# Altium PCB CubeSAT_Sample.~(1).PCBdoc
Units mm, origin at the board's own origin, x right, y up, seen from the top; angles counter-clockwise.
Board outline 90.17 x 95.89 mm, 2 copper layers (Top Layer, Bottom Layer); 6 components, 23 nets, 108 pads, 0 vias.
Unrouted connection lines stored in the file: 25.
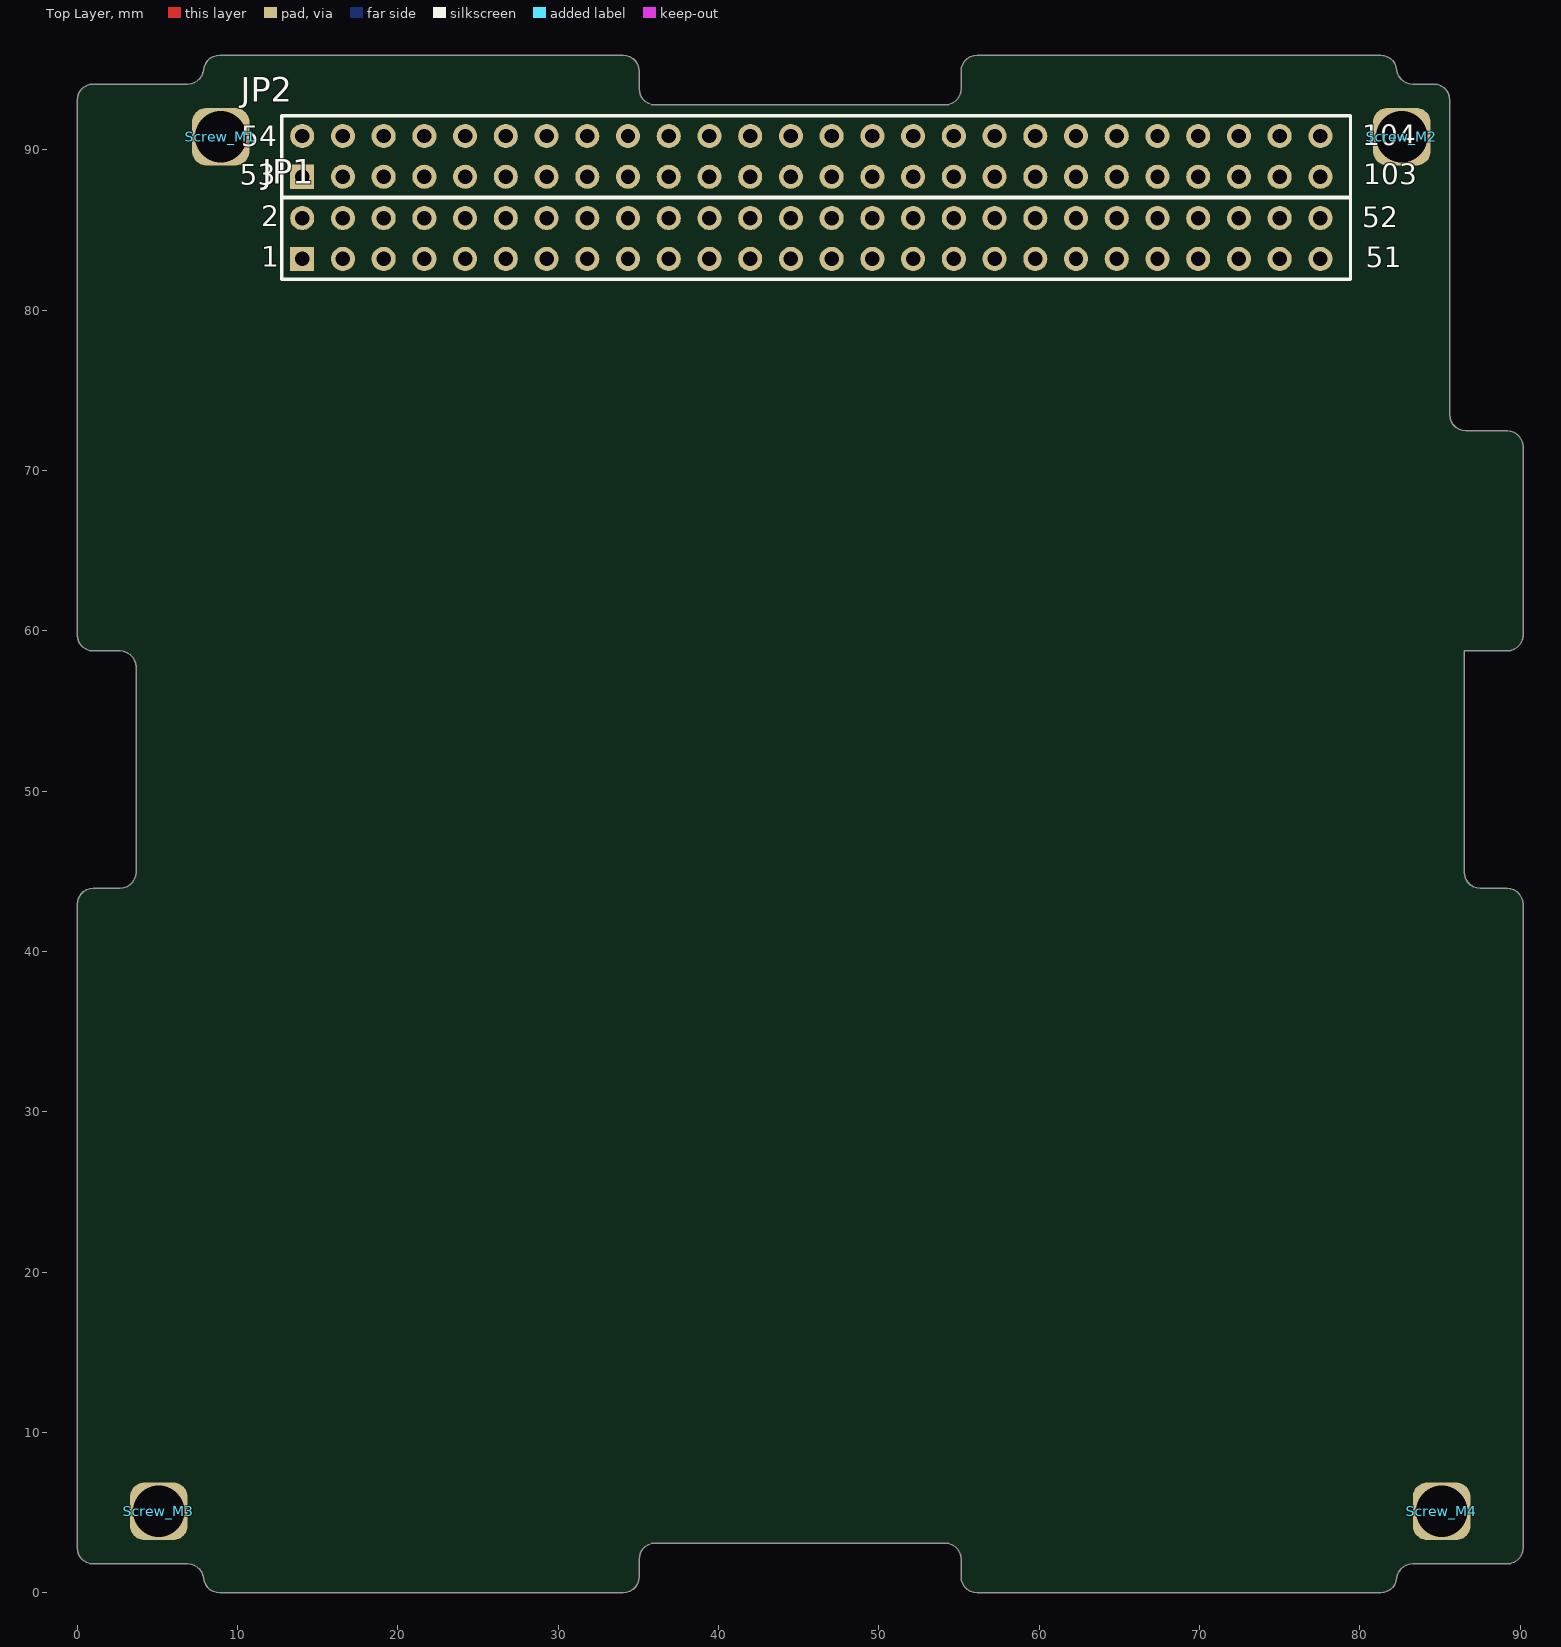
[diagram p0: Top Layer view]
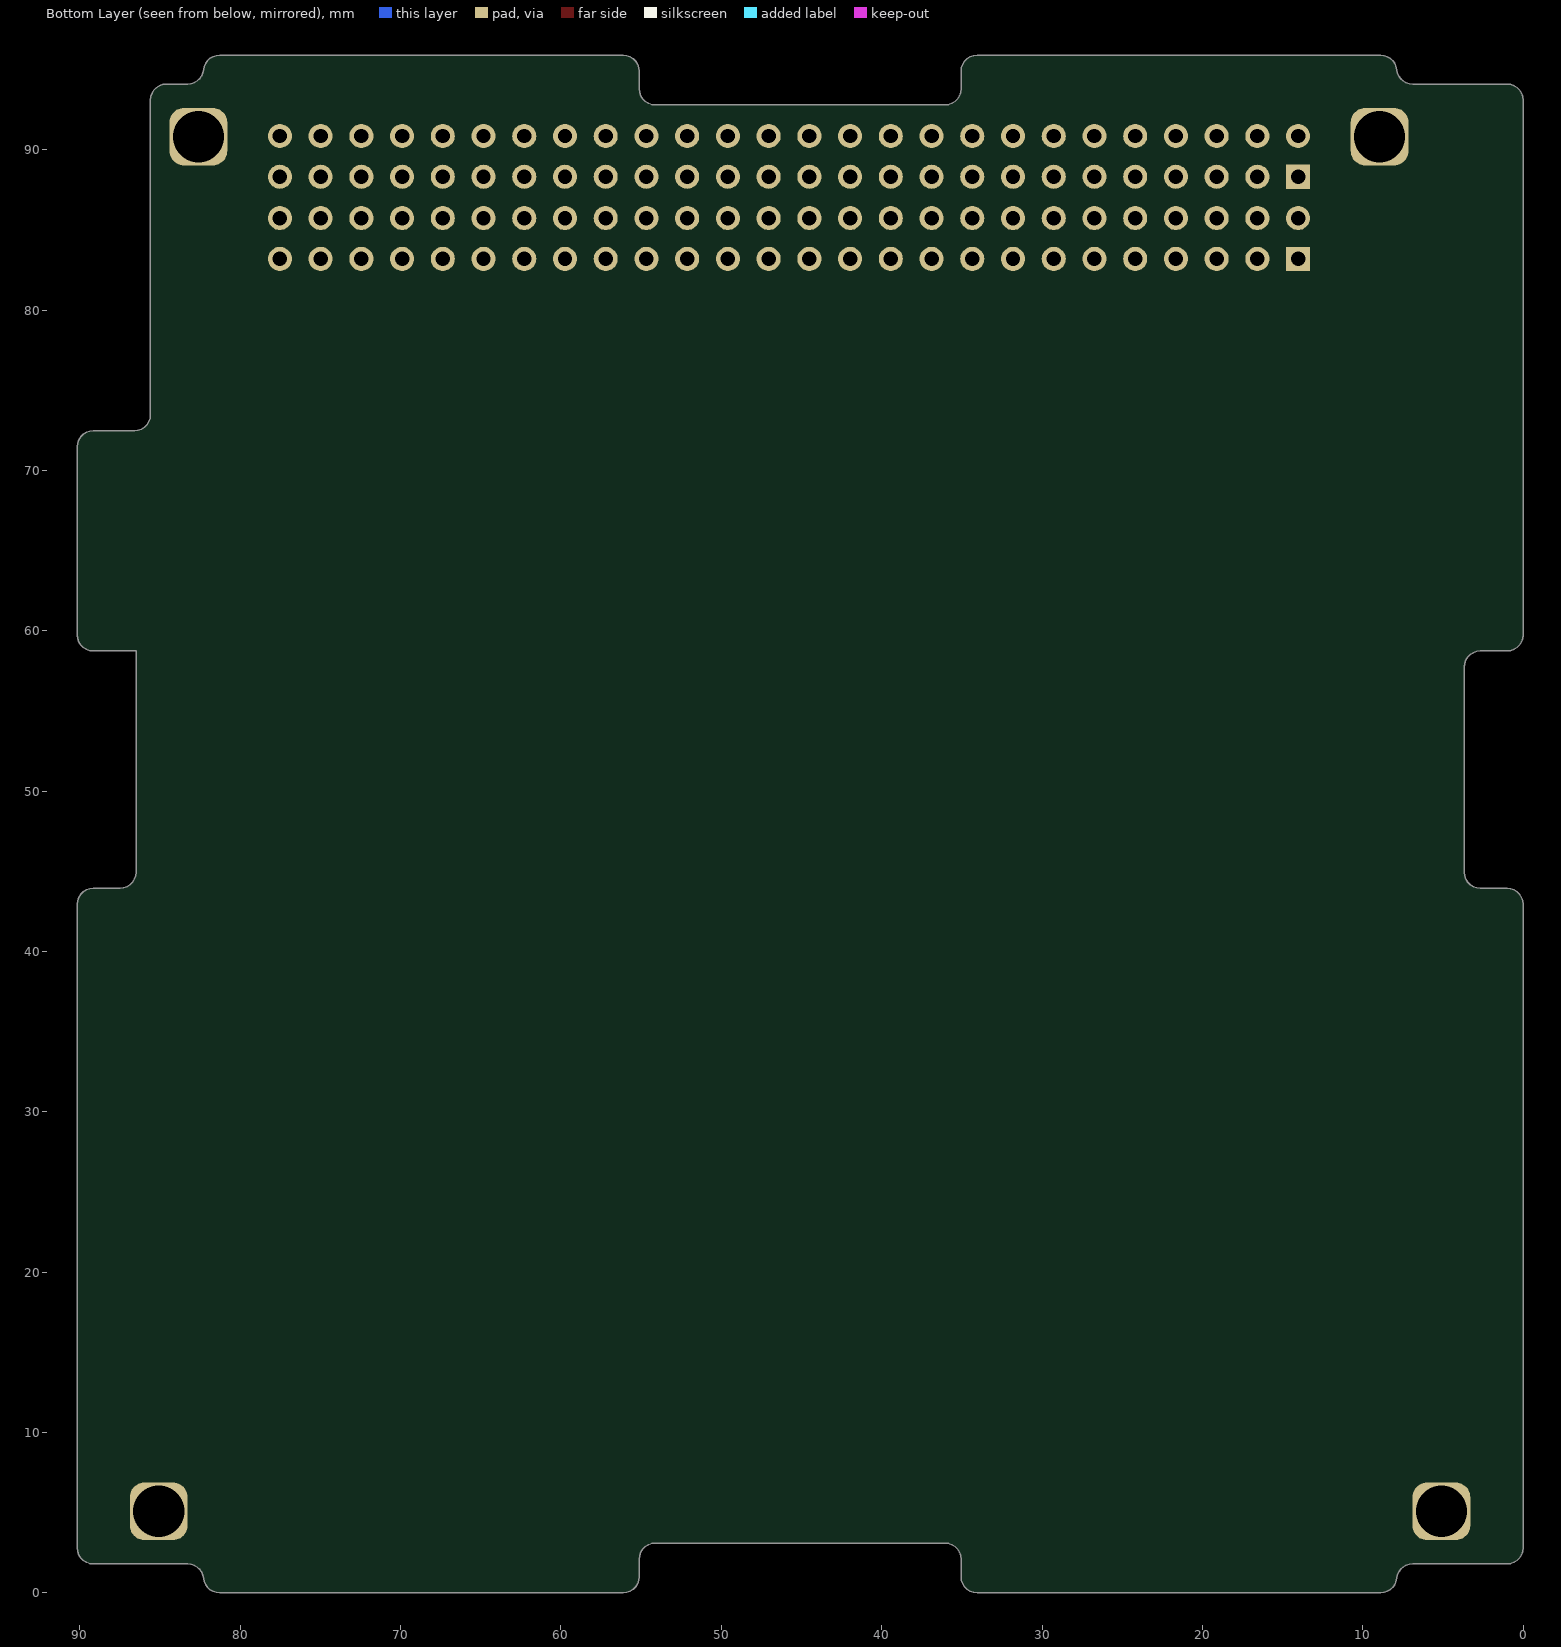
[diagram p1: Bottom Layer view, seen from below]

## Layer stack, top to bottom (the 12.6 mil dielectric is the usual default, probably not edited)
Top Solder: solder mask 0.0102, Solder Resist, Dk 3.5
Top Layer: signal copper 0.0356
Dielectric1: dielectric 0.32, FR-4, Dk 4.8
Bottom Layer: signal copper 0.0356
Bottom Solder: solder mask 0.0102, Solder Resist, Dk 3.5

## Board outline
6.889,1.8 7.098,1.778 7.297,1.713 7.478,1.608 7.634,1.467 7.757,1.297 7.841,1.105 7.884,0.9 7.927,0.695 8.011,0.503 8.134,0.333 8.29,0.192 8.471,0.087 8.67,0.022 8.879,0 34.049,0 34.271,0.025 34.483,0.099 34.672,0.218 34.831,0.376 34.95,0.566 35.024,0.777 35.049,1 35.049,2.101 35.074,2.323 35.148,2.535 35.267,2.724 35.425,2.883 35.615,3.002 35.826,3.076 36.049,3.101 54.121,3.101 54.344,3.076 54.555,3.002 54.745,2.883 54.903,2.724 55.022,2.535 55.096,2.323 55.121,2.101 55.121,1 55.146,0.777 55.22,0.566 55.339,0.376 55.498,0.218 55.687,0.099 55.899,0.025 56.121,0 81.291,0 81.5,0.022 81.699,0.087 81.88,0.192 82.036,0.333 82.159,0.503 82.243,0.695 82.286,0.9 82.329,1.105 82.413,1.297 82.536,1.467 82.692,1.608 82.873,1.713 83.072,1.778 83.281,1.8 89.17,1.8 89.393,1.825 89.604,1.899 89.793,2.018 89.952,2.177 90.071,2.366 90.145,2.577 90.17,2.8 90.17,42.937 90.145,43.159 90.071,43.371 89.952,43.56 89.793,43.719 89.604,43.838 89.393,43.912 89.17,43.937 87.5,43.937 87.277,43.962 87.066,44.036 86.876,44.155 86.718,44.313 86.599,44.503 86.525,44.714 86.5,44.937 86.5,58.735 89.17,58.735 89.393,58.76 89.604,58.834 89.793,58.953 89.952,59.111 90.071,59.301 90.145,59.512 90.17,59.735 90.17,71.466 90.145,71.689 90.071,71.9 89.952,72.089 89.793,72.248 89.604,72.367 89.393,72.441 89.17,72.466 86.6,72.466 86.377,72.491 86.166,72.565 85.977,72.684 85.818,72.843 85.699,73.032 85.625,73.243 85.6,73.466 85.6,93.091 85.575,93.314 85.501,93.525 85.382,93.714 85.223,93.873 85.034,93.992 84.823,94.066 84.6,94.091 83.281,94.091 83.073,94.113 82.873,94.178 82.692,94.283 82.536,94.424 82.414,94.593 82.329,94.785 82.286,94.99 82.243,95.196 82.159,95.387 82.036,95.557 81.88,95.698 81.699,95.803 81.5,95.868 81.291,95.89 56.121,95.89 55.899,95.865 55.687,95.791 55.498,95.672 55.339,95.513 55.22,95.324 55.146,95.113 55.121,94.89 55.121,93.789 55.096,93.567 55.022,93.355 54.903,93.166 54.745,93.007 54.555,92.888 54.344,92.814 54.121,92.789 36.049,92.789 35.826,92.814 35.615,92.888 35.425,93.007 35.267,93.166 35.148,93.355 35.074,93.567 35.049,93.789 35.049,94.89 35.024,95.113 34.95,95.324 34.831,95.513 34.672,95.672 34.483,95.791 34.271,95.865 34.049,95.89 8.879,95.89 8.67,95.868 8.471,95.803 8.29,95.698 8.134,95.557 8.011,95.387 7.927,95.196 7.884,94.99 7.841,94.785 7.756,94.593 7.634,94.424 7.478,94.283 7.297,94.178 7.097,94.113 6.889,94.091 1,94.091 0.777,94.066 0.566,93.992 0.376,93.873 0.218,93.714 0.099,93.525 0.025,93.314 0,93.091 0,59.735 0.025,59.512 0.099,59.301 0.218,59.111 0.376,58.953 0.566,58.834 0.777,58.76 1,58.735 2.67,58.735 2.893,58.71 3.104,58.636 3.293,58.517 3.452,58.358 3.571,58.169 3.645,57.957 3.67,57.735 3.67,44.937 3.645,44.714 3.571,44.503 3.452,44.313 3.293,44.155 3.104,44.036 2.893,43.962 2.67,43.937 1,43.937 0.777,43.912 0.566,43.838 0.376,43.719 0.218,43.56 0.099,43.371 0.025,43.159 0,42.937 0,2.8 0.025,2.577 0.099,2.366 0.218,2.177 0.376,2.018 0.566,1.899 0.777,1.825 1,1.8

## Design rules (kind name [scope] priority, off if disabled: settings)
Clearance [All] p1: gap=0.127 except(0.051: SMDPad-SMDPad)
ComponentClearance [All] p1: gap=0 collisioncheckmode=3 verticalgap=0.254 showdistances=FALSE
FabricationTestPointUsage TestPointUsage [All] p1: valid=0 allowmultiple=FALSE
FabricationTestpoint Testpoint [All] p1: side=3 testpointundercomponent=TRUE minsize=1.016 maxsize=2.54 preferedsize=1.524 minholesize=0 maxholesize=1.016 preferedholesize=0.813 testpointgrid=0.025 allowsidetop=TRUE allowsidebottom=TRUE usegrid=TRUE gridtolerance=0
PlaneClearance [All] p1: clearance=0.127
PlaneConnect [All] p1: planeconnectstyle=Direct reliefexpansion=0.508 reliefentries=4 reliefconductorwidth=0.254 reliefairgap=0.254
PolygonConnect [All] p1: connectstyle=Direct reliefconductorwidth=0.254 reliefentries=4 polygonreliefangle="90 Angle" airgapwidth=0.254
RoomDefinition Connectors [InComponentClass('Connectors')] p1: confinementstyle=ConfineIn formatcopy=TRUE lockcomponents=FALSE outline -107.95,-62.23 -57.15,-62.23 -57.15,-36.83 -107.95,-36.83
RoutingVias [All] p1: holewidth=0.711 width=1.27 viastyle="Through Hole" minholewidth=0.3 minwidth=0.6 maxholewidth=0.5 maxwidth=1
SilkToSolderMaskClearance SilkscreenOverComponentPads [IsPad] p1: minsilkscreentomaskgap=0.254 clearancetoexposedcopper=TRUE
SolderMaskExpansion [All] p1: expansion=0.102
Width [All] p1: maxlimit=1.016 minlimit=0.254 preferedwidth=0.254
24 further rules are at their usual default settings.

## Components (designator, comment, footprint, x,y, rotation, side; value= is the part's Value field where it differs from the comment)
JP1 "ESQ-126-39-G-D" ESQ-126-39-G-D_R 14.03,83.19 r0 top locked
JP2 "ESQ-126-39-G-D_53-104" ESQ-126-39-G-D_53_104 14.03,88.31 r0 top locked
Screw_M1 "SC1" Screw_M3#1 97.05,18.77 r90 top
Screw_M2 "SC1" Screw_M3#2 110.05,18.77 r90 top
Screw_M3 "SC1" Screw_M3#3 8.855,4.039 r90 top
Screw_M4 "SC1" Screw_M3#4 84.709,6.35 r90 top

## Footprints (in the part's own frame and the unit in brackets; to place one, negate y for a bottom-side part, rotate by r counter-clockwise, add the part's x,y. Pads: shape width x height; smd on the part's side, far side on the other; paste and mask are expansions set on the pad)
ESQ-126-39-G-D_53_104 [mm] "Cubesat Connector; Header; 26x2 Position"
  rect 1.5x1.5 hole 0.9: 53(0,0)
  round 1.5 hole 0.9: 54(0,2.54) 55(2.54,0) 56(2.54,2.54) 57(5.08,0) 58(5.08,2.54) 59(7.62,0) 60(7.62,2.54) 61(10.16,0) 62(10.16,2.54) 63(12.7,0) 64(12.7,2.54) 65(15.24,0) 66(15.24,2.54) 67(17.78,0) 68(17.78,2.54) 69(20.32,0) 70(20.32,2.54) 71(22.86,0) 72(22.86,2.54) 73(25.4,0) 74(25.4,2.54) 75(27.94,0) 76(27.94,2.54) 77(30.48,0) 78(30.48,2.54) 79(33.02,0) 80(33.02,2.54) 81(35.56,0) 82(35.56,2.54) 83(38.1,0) 84(38.1,2.54) 85(40.64,0) 86(40.64,2.54) 87(43.18,0) 88(43.18,2.54) 89(45.72,0) 90(45.72,2.54) 91(48.26,0) 92(48.26,2.54) 93(50.8,0) 94(50.8,2.54) 95(53.34,0) 96(53.34,2.54) 97(55.88,0) 98(55.88,2.54) 99(58.42,0) 100(58.42,2.54) 101(60.96,0) 102(60.96,2.54) 103(63.5,0) 104(63.5,2.54)
  silkscreen extent -1.27,-1.27 65.38,3.81, body extent -1.3,-1.3 65.25,3.78, height 10.51
ESQ-126-39-G-D_R [mm] "Cubesat Connector; Header; 26x2 Position"
  rect 1.5x1.5 hole 0.9: 1(0,0)
  round 1.5 hole 0.9: 2(0,2.54) 3(2.54,0) 4(2.54,2.54) 5(5.08,0) 6(5.08,2.54) 7(7.62,0) 8(7.62,2.54) 9(10.16,0) 10(10.16,2.54) 11(12.7,0) 12(12.7,2.54) 13(15.24,0) 14(15.24,2.54) 15(17.78,0) 16(17.78,2.54) 17(20.32,0) 18(20.32,2.54) 19(22.86,0) 20(22.86,2.54) 21(25.4,0) 22(25.4,2.54) 23(27.94,0) 24(27.94,2.54) 25(30.48,0) 26(30.48,2.54) 27(33.02,0) 28(33.02,2.54) 29(35.56,0) 30(35.56,2.54) 31(38.1,0) 32(38.1,2.54) 33(40.64,0) 34(40.64,2.54) 35(43.18,0) 36(43.18,2.54) 37(45.72,0) 38(45.72,2.54) 39(48.26,0) 40(48.26,2.54) 41(50.8,0) 42(50.8,2.54) 43(53.34,0) 44(53.34,2.54) 45(55.88,0) 46(55.88,2.54) 47(58.42,0) 48(58.42,2.54) 49(60.96,0) 50(60.96,2.54) 51(63.5,0) 52(63.5,2.54)
  silkscreen extent -1.27,-1.27 65.38,3.81, body extent -1.3,-1.3 65.25,3.78, height 10.51
Screw_M3#1 [mm] "Main CubeSAT bus M3 screw"
  rrect50% 3.6x3.6 hole 3.2: 1(72.04,88.1)
Screw_M3#2 [mm] "Main CubeSAT bus M3 screw"
  rrect50% 3.6x3.6 hole 3.2: 1(72.04,27.44)
Screw_M3#3 [mm] "Main CubeSAT bus M3 screw"
  rrect50% 3.6x3.6 hole 3.2: 1(1.041,3.765)
Screw_M3#4 [mm] "Main CubeSAT bus M3 screw"
  rrect50% 3.6x3.6 hole 3.2: 1(-1.27,-0.381)

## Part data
JP1 JP2: "Cubesat Header Connector"
Screw_M1 Screw_M2 Screw_M3 Screw_M4: library part Screw_M3, "Main CubeSAT bus"

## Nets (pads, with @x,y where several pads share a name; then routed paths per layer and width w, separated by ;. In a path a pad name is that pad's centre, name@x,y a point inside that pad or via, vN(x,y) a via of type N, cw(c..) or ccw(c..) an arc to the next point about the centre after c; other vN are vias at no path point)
+5V: JP2.77 JP2.78
"BUS3 GPIO0": JP2.64
"BUS3 GPIO1": JP2.63
"BUS3 GPIO2": JP2.66
"BUS3 GPIO3": JP2.65
"BUS4 CLK": JP1.35
"BUS4 CS": JP1.40
"BUS4 GPIO0": JP1.7
"BUS4 GPIO1": JP1.6
"BUS4 GPIO2": JP1.9
"BUS4 MISO": JP1.37
"BUS4 MOSI": JP1.39
"BUS4 RST": JP1.11
BUS6: JP2.57
"EN R PA BEACON": JP1.8
GND: JP1.1 JP1.2 JP1.3 JP1.4 JP1.29 JP1.30 JP1.31 JP1.32 JP2.53 JP2.54 JP2.55 JP2.56 JP2.61 JP2.73 JP2.74 JP2.81 JP2.82 JP2.83 JP2.84
"R ANT": JP2.87 JP2.88
"R EPS/BEACON": JP2.80
"R PA BEACON": JP1.51 JP1.52
"R PA TRANSC": JP1.49 JP1.50
SCLC: JP1.43
SDAC: JP1.41
SGND: Screw_M1.1 Screw_M2.1 Screw_M3.1 Screw_M4.1
pads on no net: JP1.5 JP1.10 JP1.12 JP1.13 JP1.14 JP1.15 JP1.16 JP1.17 JP1.18 JP1.19 JP1.20 JP1.21 JP1.22 JP1.23 JP1.24 JP1.25 JP1.26 JP1.27 JP1.28 JP1.33 JP1.34 JP1.36 JP1.38 JP1.42 JP1.44 JP1.45 JP1.46 JP1.47 JP1.48 JP2.58 JP2.59 JP2.60 JP2.62 JP2.67 JP2.68 JP2.69 JP2.70 JP2.71 JP2.72 JP2.75 JP2.76 JP2.79 JP2.85 JP2.86 JP2.89 JP2.90 JP2.91 JP2.92 JP2.93 JP2.94 JP2.95 JP2.96 JP2.97 JP2.98 JP2.99 JP2.100 JP2.101 JP2.102 JP2.103 JP2.104

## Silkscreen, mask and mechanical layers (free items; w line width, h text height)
Mechanical 16:
  drawing of 8377 lines, arcs and shapes, not listed
  text "1" at -66.624,132.461 h1.78
  text "2" at 6.02,132.461 h1.78
  text "3" at 79.172,132.461 h1.78
  text "4" at 152.07,132.461 h1.78
  text "A" at -100.965,109.449 h1.78
  text "A" at 186.055,109.449 h1.78
  text "B" at -100.965,61.392 h1.78
  text "B" at 186.055,61.392 h1.78
  text "D" at 55.845,21.107 h1.78
  text "C" at -100.965,12.878 h1.78
  text "C" at 186.055,12.878 h1.78
  text "Designer's signature:" at 36.576,-30.226 h1.02
  text "Dpto. Electronica y Tecnologia" at 128.524,-31.496 h1.27
  text "Sheet title: PUT YOUR TITLE" at 65.278,-32.258 h1.52
  text "de Computadores" at 128.524,-34.036 h1.27
  text "D" at 186.055,-35.128 h1.78
  text "University of Granada" at 128.524,-36.322 h1.27
  text "Project title: PUT YOUR PROJECT NAME" at 65.278,-38.608 h1.52
  text "C/ Fuente Nueva, s/n, 18001" at 128.524,-38.608 h1.27
  text "Granada, Granada, Spain" at 128.524,-41.148 h1.27
  text "Supervisor's signature:" at 36.83,-42.672 h1.02
  text "Sr. Andres Roldan Aranda" at 128.524,-43.688 h1.27
  text "Designer: Private Pyle" at 65.278,-44.45 h1.52
  text "Date: 01.03.2015" at 128.016,-48.514 h1.02
  text "Revision: 1" at 144.272,-48.514 h1.02
  text "Supervisor: Andres Roldan Aranda" at 65.278,-50.292 h1.52
  text "Sheet 1 of 10" at 128.016,-51.054 h1.02
  text "3" at 79.172,-55.499 h1.78
  text "4" at 152.07,-55.499 h1.78

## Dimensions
0,0 to -1,96 on Mechanical 16
0,94.894 to 90.17,95.936 on Mechanical 16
